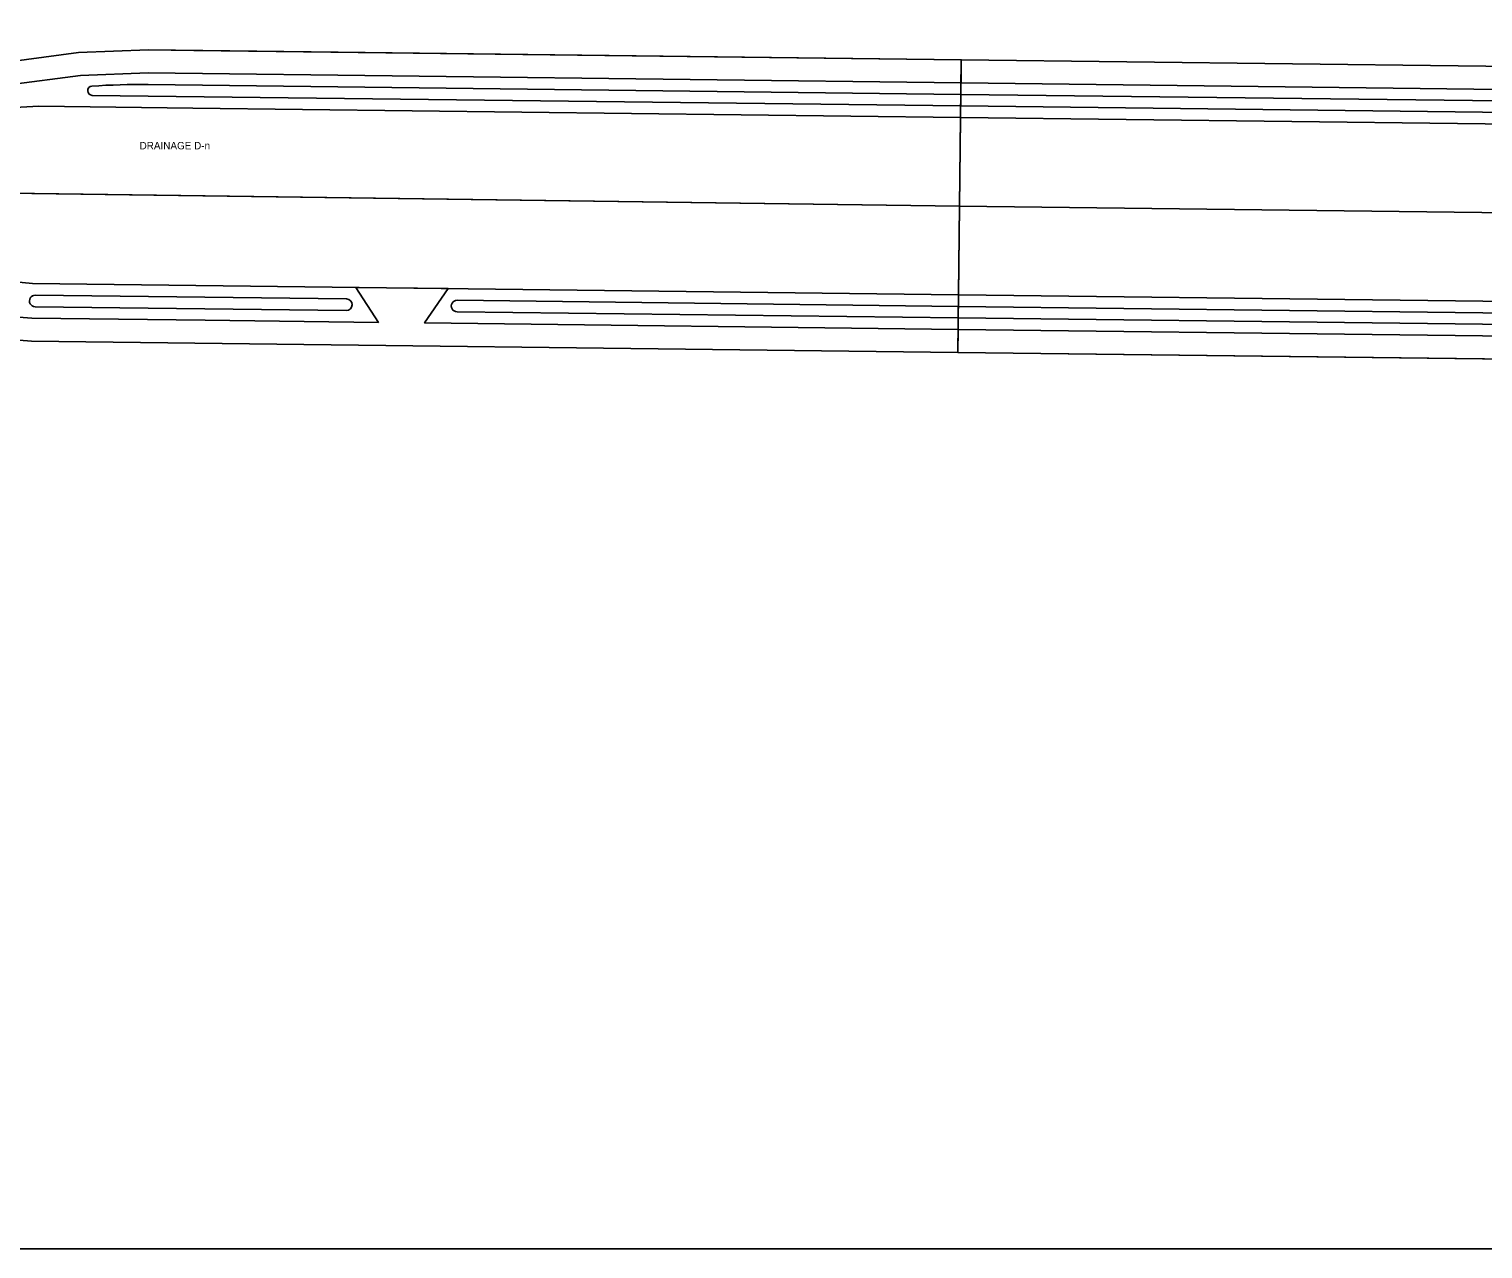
# Model space of a CAD drawing. Extents: x 2342969 to 2348591, y 2217407 to 2218312.
# Drawn here: x 2346061 to 2346692, y 2217407 to 2217936 of the extents above; entities that cross this region are included whole.
import ezdxf

# ---------------------------------------------------------------- set-up
doc = ezdxf.new("R2010")
doc.units = 0
doc.layers.add('TOPO_CURBGTR_Lip-of-Gutter', color=7, linetype='Continuous')
doc.layers.add('TOPO_SW_Edge', color=7, linetype='Continuous')

msp = doc.modelspace()

# ---------------------------------------------------------------- linework, layer by layer
at = {"layer": 'TOPO_CURBGTR_Lip-of-Gutter'}
for p, q in [((2346198.57, 2217813.9), (2346063.56, 2217815.54)), ((2346063.62, 2217820.54), (2346198.64, 2217818.9))]:
    msp.add_line(p, q, dxfattribs=at)
for points in [[(2346052.13, 2217901.84), (2346051.62, 2217864.84), (2346464.66, 2217859.17), (2346465.43, 2217922.67), (2346132.4, 2217926.71), (2346112.76, 2217926.95), (2346082.4, 2217925.83), (2346052.3, 2217921.75)], [(2346052.21, 2217911.79), (2346083.26, 2217915.87), (2346112.64, 2217916.95), (2346465.31, 2217912.67), (2346465.43, 2217922.67), (2346112.76, 2217926.95), (2346082.4, 2217925.83), (2346052.3, 2217921.75)], [(2346465.43, 2217922.67), (2346464.66, 2217859.17), (2348027, 2217840.19), (2348027.13, 2217899.19), (2347874.53, 2217901.04), (2347721.93, 2217902.9), (2347700.27, 2217902.04), (2347678.82, 2217898.96), (2347659.4, 2217896.17), (2347639.81, 2217895.39), (2347444.37, 2217897.77), (2347429.75, 2217899.02), (2347415.47, 2217902.41), (2347399.75, 2217906.13), (2347383.67, 2217907.51), (2347312.05, 2217908.38), (2347240.42, 2217909.25), (2347040.49, 2217915.68)], [(2346465.25, 2217907.67), (2346465.19, 2217902.67), (2346882.17, 2217897.6), (2347040.14, 2217895.68), (2347240.08, 2217889.25), (2347410.7, 2217887.18), (2347411.01, 2217889.13), (2347404.25, 2217890.98), (2347397.23, 2217892.34), (2347240.14, 2217894.25), (2347040.2, 2217900.68), (2346724.25, 2217904.52)], [(2346052.13, 2217901.84), (2346051.62, 2217864.84), (2346464.66, 2217859.17), (2346465.13, 2217897.67), (2346132.01, 2217901.72), (2346065.16, 2217902.53)], [(2346465.13, 2217897.67), (2347040.08, 2217890.68), (2347240.02, 2217884.25), (2347844.98, 2217876.9), (2348027.08, 2217878.33), (2348027, 2217840.19), (2346464.66, 2217859.17)], [(2345714.74, 2217869.46), (2345769.13, 2217798.48), (2345785.53, 2217787.68), (2345795.52, 2217788.16), (2345796.49, 2217796.45), (2345797.95, 2217802.62), (2345803.51, 2217811.94), (2345811, 2217818.62), (2345820.21, 2217822.62), (2345831.17, 2217824.29), (2345835.2, 2217823.92), (2345873.87, 2217818), (2345932.75, 2217811.07), (2345991.97, 2217808.22), (2346010.47, 2217807.98), (2346020.12, 2217807.22), (2346029.6, 2217805.21), (2346045.63, 2217801.83), (2346061.97, 2217800.56), (2346463.89, 2217795.68), (2346464.66, 2217859.17)], [(2346464.66, 2217859.17), (2348027, 2217840.18), (2348026.89, 2217787.07), (2348009.69, 2217787.62), (2347892.7, 2217791.38), (2347844.1, 2217787.9), (2347729.58, 2217789.3), (2347725.62, 2217784.34), (2347482.3, 2217787.3), (2347238.98, 2217790.26), (2347038.94, 2217788.69), (2346728.44, 2217792.46), (2346463.89, 2217795.68)], [(2346464.66, 2217859.17), (2346464.19, 2217820.67), (2347039.15, 2217813.69), (2347239.18, 2217815.26), (2347844.14, 2217807.9), (2348026.92, 2217802.03), (2348027, 2217840.18)], [(2346464.01, 2217805.67), (2347038.97, 2217798.69), (2347239, 2217800.26), (2347729.64, 2217794.3), (2347843.95, 2217792.91), (2347892.61, 2217796.39), (2348010.22, 2217792.61), (2348026.9, 2217792.07), (2348026.89, 2217787.07), (2348009.69, 2217787.62), (2347892.7, 2217791.38), (2347844.1, 2217787.9), (2347729.58, 2217789.3), (2347725.62, 2217784.34), (2347238.98, 2217790.26), (2347038.94, 2217788.69), (2346463.89, 2217795.68)]]:
    msp.add_lwpolyline(points, close=True, dxfattribs=at)
for points in [[(2347639.81, 2217895.39), (2347444.37, 2217897.77), (2347429.75, 2217899.02), (2347415.47, 2217902.41), (2347399.75, 2217906.13), (2347383.67, 2217907.51), (2347240.42, 2217909.25), (2347040.49, 2217915.68), (2346465.43, 2217922.67), (2346465.31, 2217912.67), (2346875.28, 2217907.68), (2347040.27, 2217905.68), (2347140.23, 2217902.47), (2347240.2, 2217899.25), (2347383.55, 2217897.51), (2347398.17, 2217896.25), (2347412.45, 2217892.87), (2347428.17, 2217889.15), (2347444.25, 2217887.77), (2347639.69, 2217885.39)], [(2346112.57, 2217911.95), (2346465.25, 2217907.67), (2346465.19, 2217902.67), (2346088.33, 2217907.25)], [(2346045.7, 2217827.14), (2346062.36, 2217825.56), (2346464.19, 2217820.67), (2346464.66, 2217859.17), (2345714.74, 2217869.46)], [(2346045.63, 2217801.83), (2346061.97, 2217800.56), (2346463.89, 2217795.68), (2346464.01, 2217805.67), (2346232.52, 2217808.49), (2346242.71, 2217823.37), (2346202.71, 2217823.85), (2346212.53, 2217808.73), (2346137.31, 2217809.64), (2346062.09, 2217810.56), (2346047.05, 2217811.73)], [(2346246.66, 2217818.32), (2346464.13, 2217815.67), (2346464.07, 2217810.67), (2346246.6, 2217813.32)], [(2347611.54, 2217800.73), (2347239.06, 2217805.26), (2347039.03, 2217803.69), (2346464.07, 2217810.67), (2346464.13, 2217815.67), (2347039.09, 2217808.69), (2347239.12, 2217810.26), (2347633.4, 2217805.47)]]:
    msp.add_lwpolyline(points, dxfattribs=at)
for centre, radius, start, end in [((2346088.35, 2217909.25), 2, 94.03886, 269.30378), ((2346108.99, 2217616.97), 295, 89.30378, 94.03886), ((2346063.59, 2217818.04), 2.5, 89.30378, 269.30378), ((2346198.6, 2217816.4), 2.5, 269.30378, 89.30378), ((2346246.63, 2217815.82), 2.5, 89.30378, 269.30378)]:
    msp.add_arc(centre, radius, start, end, dxfattribs=at)
at = {"layer": 'TOPO_SW_Edge'}
msp.add_line((2346463.89, 2217795.68), (2346465.43, 2217922.67), dxfattribs=at)
msp.add_lwpolyline([(2345930.36, 2218312.45), (2348590.54, 2218312.45), (2348590.54, 2217406.65), (2345930.36, 2217406.65)], close=True, dxfattribs=at)

# ---------------------------------------------------------------- texts
msp.add_text('DRAINAGE D-n', height=3.216, dxfattribs=at).set_placement((2346108.87, 2217883.81))

doc.saveas('drawing.dxf')
